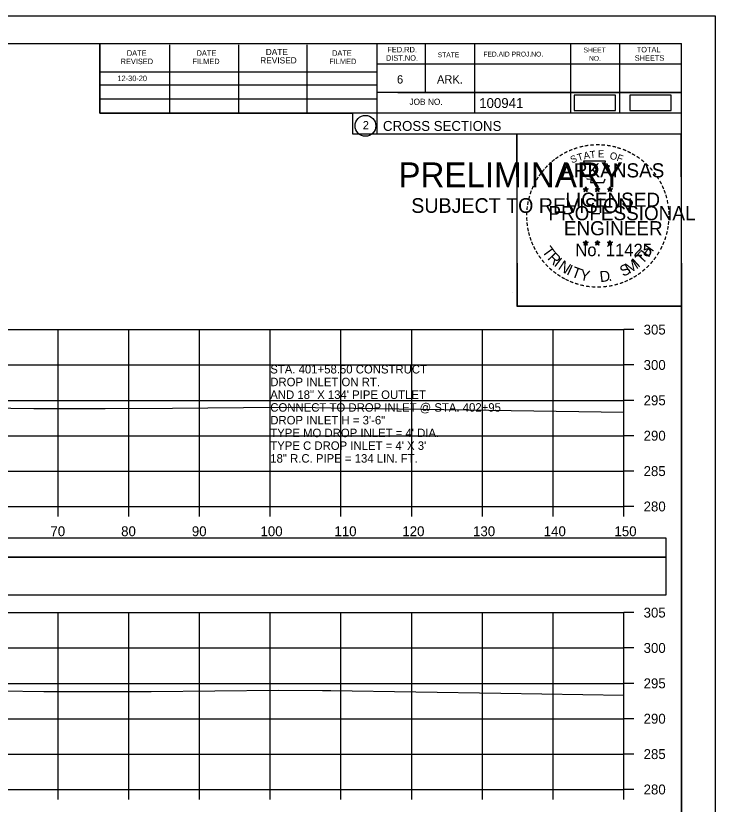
# Model space of a CAD drawing. Extents: x 1370538 to 1372872, y 376220 to 381127.
# Drawn here: x 1370772.6 to 1370871.5, y 376322.3 to 376433.8 of the extents above; entities that cross this region are included whole.
import ezdxf

# ---------------------------------------------------------------- set-up
doc = ezdxf.new("R2010")
doc.units = 0
for name, color, linetype in [('Default', 7, 'Continuous'), ('R_Border Notes', 7, 'Continuous'), ('R_Border PE', 7, 'Continuous'), ('R_Border Prem', 7, 'Continuous'), ('R_Dimension', 7, 'Continuous'), ('R_Grid', 7, 'Continuous'), ('R_No Plot', 7, 'Continuous'), ('R_Water Annot', 7, 'Continuous'), ('T_Detection Zones', 7, 'Continuous'), ('T_Indications', 7, 'Continuous'), ('T_Notes', 7, 'Continuous')]:
    doc.layers.add(name, color=color, linetype=linetype)

msp = doc.modelspace()

# ---------------------------------------------------------------- linework, layer by layer
at = {"layer": 'Default'}
for points in [[(1370851.6, 376420.37), (1370857.43, 376420.37), (1370857.43, 376422.56), (1370851.6, 376422.56)], [(1370859.47, 376420.37), (1370865.3, 376420.37), (1370865.3, 376422.56), (1370859.47, 376422.56)]]:
    msp.add_lwpolyline(points, close=True, dxfattribs=at)
at = {"layer": 'R_Border Notes'}
for p, q in [((1370550.61, 376429.87), (1370866.79, 376429.87)), ((1370784.53, 376419.99), (1370784.53, 376429.87)), ((1370794.39, 376419.99), (1370794.39, 376429.67)), ((1370804.15, 376419.99), (1370804.15, 376429.67)), ((1370813.83, 376419.99), (1370813.83, 376429.67)), ((1370823.69, 376429.87), (1370823.69, 376417.07)), ((1370830.53, 376429.87), (1370830.53, 376422.93)), ((1370837.47, 376429.87), (1370837.47, 376419.99)), ((1370851.05, 376429.87), (1370851.05, 376419.99)), ((1370857.99, 376429.87), (1370857.99, 376419.99)), ((1370866.79, 376224.41), (1370866.79, 376429.87)), ((1370866.79, 376426.93), (1370823.69, 376426.93)), ((1370866.79, 376426.95), (1370866.79, 376426.95)), ((1370784.53, 376425.85), (1370823.69, 376425.85)), ((1370784.53, 376423.99), (1370823.69, 376423.99)), ((1370866.79, 376422.93), (1370823.69, 376422.93)), ((1370826.65, 376422.93), (1370866.79, 376422.93)), ((1370784.53, 376419.99), (1370784.53, 376422.05)), ((1370784.53, 376422.05), (1370823.69, 376422.05)), ((1370866.79, 376419.99), (1370784.53, 376419.99)), ((1370823.69, 376417.07), (1370866.79, 376417.07))]:
    msp.add_line(p, q, dxfattribs=at)
msp.add_circle((1370822.07, 376418.21), 1.47, dxfattribs=at)
at = {"layer": 'R_Border Prem'}
for p, q in [((1370858.61, 376364.41), (1370858.61, 376389.41)), ((1370860.01, 376389.41), (1370858.61, 376389.41)), ((1370860.01, 376384.41), (1370858.61, 376384.41)), ((1370860.01, 376379.41), (1370858.61, 376379.41)), ((1370860.01, 376374.41), (1370858.61, 376374.41)), ((1370860.01, 376369.41), (1370858.61, 376369.41)), ((1370558.61, 376364.41), (1370858.61, 376364.41)), ((1370778.61, 376363.01), (1370778.61, 376364.41)), ((1370788.61, 376363.01), (1370788.61, 376364.41)), ((1370798.61, 376363.01), (1370798.61, 376364.41)), ((1370808.61, 376363.01), (1370808.61, 376364.41)), ((1370818.61, 376363.01), (1370818.61, 376364.41)), ((1370828.61, 376363.01), (1370828.61, 376364.41)), ((1370838.61, 376363.01), (1370838.61, 376364.41)), ((1370848.61, 376363.01), (1370848.61, 376364.41)), ((1370858.61, 376363.01), (1370858.61, 376364.41)), ((1370860.01, 376364.41), (1370858.61, 376364.41)), ((1370858.61, 376324.41), (1370858.61, 376349.41)), ((1370860.01, 376349.41), (1370858.61, 376349.41)), ((1370860.01, 376344.41), (1370858.61, 376344.41)), ((1370860.01, 376339.41), (1370858.61, 376339.41)), ((1370860.01, 376334.41), (1370858.61, 376334.41)), ((1370860.01, 376329.41), (1370858.61, 376329.41)), ((1370558.61, 376324.41), (1370858.61, 376324.41)), ((1370778.61, 376323.01), (1370778.61, 376324.41)), ((1370788.61, 376323.01), (1370788.61, 376324.41)), ((1370798.61, 376323.01), (1370798.61, 376324.41)), ((1370808.61, 376323.01), (1370808.61, 376324.41)), ((1370818.61, 376323.01), (1370818.61, 376324.41)), ((1370828.61, 376323.01), (1370828.61, 376324.41)), ((1370838.61, 376323.01), (1370838.61, 376324.41)), ((1370848.61, 376323.01), (1370848.61, 376324.41)), ((1370858.61, 376323.01), (1370858.61, 376324.41)), ((1370860.01, 376324.41), (1370858.61, 376324.41))]:
    msp.add_line(p, q, dxfattribs=at)
at = {"layer": 'R_Dimension'}
for points in [[(1370765.35, 376378.4), (1370775.16, 376378.26), (1370785.24, 376378.26), (1370794.79, 376378.29), (1370809.82, 376378.47), (1370814.99, 376378.41), (1370817.22, 376378.37), (1370858.61, 376377.74)], [(1370770.61, 376338.34), (1370776.58, 376338.25), (1370788.09, 376338.25), (1370791.77, 376338.26), (1370809.78, 376338.47), (1370815.98, 376338.41), (1370817.18, 376338.38), (1370841.24, 376338.02), (1370858.61, 376337.75)]]:
    msp.add_lwpolyline(points, dxfattribs=at)
at = {"layer": 'R_Grid'}
for p, q in [((1370558.61, 376389.41), (1370858.61, 376389.41)), ((1370778.61, 376364.41), (1370778.61, 376389.41)), ((1370788.61, 376364.41), (1370788.61, 376389.41)), ((1370798.61, 376364.41), (1370798.61, 376389.41)), ((1370808.61, 376364.41), (1370808.61, 376389.41)), ((1370818.61, 376364.41), (1370818.61, 376389.41)), ((1370828.61, 376364.41), (1370828.61, 376389.41)), ((1370838.61, 376364.41), (1370838.61, 376389.41)), ((1370848.61, 376364.41), (1370848.61, 376389.41)), ((1370858.61, 376364.41), (1370858.61, 376389.41)), ((1370558.61, 376384.41), (1370858.61, 376384.41)), ((1370558.61, 376379.41), (1370858.61, 376379.41)), ((1370558.61, 376374.41), (1370858.61, 376374.41)), ((1370558.61, 376369.41), (1370858.61, 376369.41)), ((1370558.61, 376364.41), (1370858.61, 376364.41)), ((1370558.61, 376349.41), (1370858.61, 376349.41)), ((1370778.61, 376324.41), (1370778.61, 376349.41)), ((1370788.61, 376324.41), (1370788.61, 376349.41)), ((1370798.61, 376324.41), (1370798.61, 376349.41)), ((1370808.61, 376324.41), (1370808.61, 376349.41)), ((1370818.61, 376324.41), (1370818.61, 376349.41)), ((1370828.61, 376324.41), (1370828.61, 376349.41)), ((1370838.61, 376324.41), (1370838.61, 376349.41)), ((1370848.61, 376324.41), (1370848.61, 376349.41)), ((1370858.61, 376324.41), (1370858.61, 376349.41)), ((1370558.61, 376344.41), (1370858.61, 376344.41)), ((1370558.61, 376339.41), (1370858.61, 376339.41)), ((1370558.61, 376334.41), (1370858.61, 376334.41)), ((1370558.61, 376329.41), (1370858.61, 376329.41)), ((1370558.61, 376324.41), (1370858.61, 376324.41))]:
    msp.add_line(p, q, dxfattribs=at)
at = {"layer": 'R_No Plot'}
for p, q in [((1370538.21, 376433.77), (1370871.54, 376433.77)), ((1370842.82, 376394.62), (1370842.82, 376394.62))]:
    msp.add_line(p, q, dxfattribs=at)
for points in [[(1370538.2, 376433.77), (1370871.54, 376433.77), (1370871.54, 376220.43), (1370538.2, 376220.43)], [(1370784.53, 376429.87), (1370784.53, 376419.99), (1370820.26, 376419.99), (1370820.26, 376417.07), (1370843.46, 376417.07), (1370843.46, 376392.74), (1370866.79, 376392.74), (1370866.79, 376224.41), (1370550.61, 376224.41), (1370550.61, 376429.87)], [(1370843.46, 376417.07), (1370866.67, 376417.07), (1370866.79, 376392.74), (1370843.58, 376392.74)]]:
    msp.add_lwpolyline(points, close=True, dxfattribs=at)
at = {"layer": 'T_Detection Zones'}
for points in [[(1370552.62, 376357.24), (1370864.59, 376357.24), (1370864.59, 376359.94), (1370552.62, 376359.94)], [(1370552.62, 376351.91), (1370864.59, 376351.91), (1370864.59, 376357.24), (1370552.62, 376357.24)]]:
    msp.add_lwpolyline(points, close=True, dxfattribs=at)
at = {"layer": 'T_Indications'}
for p, q in [((1370853.22, 376409.58), (1370853.18, 376409.33)), ((1370853.22, 376409.22), (1370853.22, 376409.58)), ((1370853.22, 376409.58), (1370853.27, 376409.33)), ((1370854.89, 376409.58), (1370854.85, 376409.33)), ((1370854.89, 376409.22), (1370854.89, 376409.58)), ((1370854.89, 376409.58), (1370854.94, 376409.33)), ((1370856.65, 376409.57), (1370856.61, 376409.32)), ((1370856.65, 376409.21), (1370856.65, 376409.57)), ((1370856.65, 376409.57), (1370856.7, 376409.32)), ((1370852.87, 376409.33), (1370853.22, 376409.22)), ((1370852.87, 376409.33), (1370853.12, 376409.28)), ((1370852.87, 376409.33), (1370853.11, 376409.21)), ((1370853, 376408.92), (1370853.22, 376409.22)), ((1370853, 376408.92), (1370853.13, 376409.17)), ((1370853, 376408.92), (1370853.22, 376409.14)), ((1370853.57, 376409.33), (1370853.22, 376409.22)), ((1370853.43, 376408.92), (1370853.22, 376409.22)), ((1370853.43, 376408.92), (1370853.22, 376409.14)), ((1370853.57, 376409.33), (1370853.28, 376409.28)), ((1370853.43, 376408.92), (1370853.3, 376409.21)), ((1370853.57, 376409.33), (1370853.36, 376409.23)), ((1370854.54, 376409.33), (1370854.89, 376409.22)), ((1370854.54, 376409.33), (1370854.79, 376409.28)), ((1370854.54, 376409.33), (1370854.78, 376409.21)), ((1370854.67, 376408.92), (1370854.89, 376409.22)), ((1370854.67, 376408.92), (1370854.8, 376409.17)), ((1370854.67, 376408.92), (1370854.89, 376409.14)), ((1370855.24, 376409.33), (1370854.89, 376409.22)), ((1370855.1, 376408.92), (1370854.89, 376409.22)), ((1370855.1, 376408.92), (1370854.89, 376409.14)), ((1370855.24, 376409.33), (1370854.95, 376409.28)), ((1370855.1, 376408.92), (1370854.97, 376409.21)), ((1370855.24, 376409.33), (1370855.03, 376409.23)), ((1370856.31, 376409.32), (1370856.65, 376409.21)), ((1370856.31, 376409.32), (1370856.56, 376409.27)), ((1370856.31, 376409.32), (1370856.54, 376409.2)), ((1370856.44, 376408.91), (1370856.65, 376409.21)), ((1370856.44, 376408.91), (1370856.56, 376409.15)), ((1370856.44, 376408.91), (1370856.65, 376409.13)), ((1370857, 376409.32), (1370856.65, 376409.21)), ((1370856.87, 376408.91), (1370856.65, 376409.21)), ((1370856.87, 376408.91), (1370856.65, 376409.12)), ((1370857, 376409.32), (1370856.72, 376409.27)), ((1370856.87, 376408.91), (1370856.73, 376409.2)), ((1370857, 376409.32), (1370856.8, 376409.22)), ((1370853.22, 376402.01), (1370853.18, 376401.76)), ((1370853.22, 376401.65), (1370853.22, 376402.01)), ((1370853.22, 376402.01), (1370853.27, 376401.76)), ((1370854.89, 376402.01), (1370854.84, 376401.76)), ((1370854.89, 376401.65), (1370854.89, 376402.01)), ((1370854.89, 376402.01), (1370854.93, 376401.76)), ((1370856.65, 376402), (1370856.61, 376401.75)), ((1370856.65, 376401.64), (1370856.65, 376402)), ((1370856.65, 376402), (1370856.7, 376401.75)), ((1370852.87, 376401.76), (1370853.22, 376401.65)), ((1370852.87, 376401.76), (1370853.12, 376401.71)), ((1370852.87, 376401.76), (1370853.1, 376401.63)), ((1370853, 376401.35), (1370853.22, 376401.65)), ((1370853, 376401.35), (1370853.13, 376401.59)), ((1370853, 376401.35), (1370853.21, 376401.57)), ((1370853.43, 376401.35), (1370853.21, 376401.56)), ((1370853.56, 376401.76), (1370853.22, 376401.65)), ((1370853.43, 376401.35), (1370853.22, 376401.65)), ((1370853.56, 376401.76), (1370853.28, 376401.71)), ((1370853.43, 376401.35), (1370853.29, 376401.64)), ((1370853.56, 376401.76), (1370853.36, 376401.65)), ((1370854.54, 376401.76), (1370854.89, 376401.65)), ((1370854.54, 376401.76), (1370854.79, 376401.71)), ((1370854.54, 376401.76), (1370854.77, 376401.63)), ((1370854.67, 376401.35), (1370854.89, 376401.65)), ((1370854.67, 376401.35), (1370854.8, 376401.59)), ((1370854.67, 376401.35), (1370854.88, 376401.57)), ((1370855.1, 376401.35), (1370854.88, 376401.56)), ((1370855.23, 376401.76), (1370854.89, 376401.65)), ((1370855.1, 376401.35), (1370854.89, 376401.65)), ((1370855.23, 376401.76), (1370854.95, 376401.71)), ((1370855.1, 376401.35), (1370854.96, 376401.64)), ((1370855.23, 376401.76), (1370855.03, 376401.65)), ((1370856.3, 376401.75), (1370856.65, 376401.64)), ((1370856.3, 376401.75), (1370856.56, 376401.7)), ((1370856.3, 376401.75), (1370856.54, 376401.62)), ((1370856.44, 376401.34), (1370856.65, 376401.64)), ((1370856.44, 376401.34), (1370856.56, 376401.58)), ((1370856.44, 376401.34), (1370856.65, 376401.56)), ((1370857, 376401.75), (1370856.65, 376401.64)), ((1370856.87, 376401.34), (1370856.65, 376401.64)), ((1370856.87, 376401.34), (1370856.65, 376401.55)), ((1370857, 376401.75), (1370856.71, 376401.7)), ((1370856.87, 376401.34), (1370856.73, 376401.63)), ((1370857, 376401.75), (1370856.8, 376401.64))]:
    msp.add_line(p, q, dxfattribs=at)
for points in [[(1370852.91, 376413.21), (1370853.18, 376412.38)], [(1370856.42, 376412.29), (1370856.57, 376412.57), (1370855.88, 376412.55), (1370856.03, 376413.21), (1370852.91, 376413.21)], [(1370853.4, 376410.78), (1370853.4, 376410.7), (1370853.97, 376410.68), (1370853.91, 376410.21), (1370855.78, 376410.21), (1370855.98, 376410.74)], [(1370853.22, 376409.58), (1370853.43, 376408.92), (1370852.87, 376409.33), (1370853.57, 376409.33), (1370853, 376408.92), (1370853.22, 376409.58)], [(1370854.89, 376409.58), (1370855.1, 376408.92), (1370854.54, 376409.33), (1370855.24, 376409.33), (1370854.67, 376408.92), (1370854.89, 376409.58)], [(1370856.65, 376409.57), (1370856.87, 376408.91), (1370856.31, 376409.32), (1370857, 376409.32), (1370856.44, 376408.91), (1370856.65, 376409.57)], [(1370853.22, 376402.01), (1370853.43, 376401.35), (1370852.87, 376401.76), (1370853.56, 376401.76), (1370853, 376401.35), (1370853.22, 376402.01)], [(1370854.89, 376402.01), (1370855.1, 376401.35), (1370854.54, 376401.76), (1370855.23, 376401.76), (1370854.67, 376401.35), (1370854.89, 376402.01)], [(1370856.65, 376402), (1370856.87, 376401.34), (1370856.3, 376401.75), (1370857, 376401.75), (1370856.44, 376401.34), (1370856.65, 376402)]]:
    msp.add_lwpolyline(points, dxfattribs=at)
for centre, radius in [((1370853.22, 376409.22), 0.172), ((1370853.22, 376409.22), 0.145), ((1370853.22, 376409.22), 0.116), ((1370853.22, 376409.22), 0.0991), ((1370853.22, 376409.22), 0.0747), ((1370853.22, 376409.22), 0.0495), ((1370853.22, 376409.22), 0.0296), ((1370854.89, 376409.22), 0.172), ((1370854.89, 376409.22), 0.145), ((1370854.89, 376409.22), 0.116), ((1370854.89, 376409.22), 0.0991), ((1370854.89, 376409.22), 0.0747), ((1370854.89, 376409.22), 0.0495), ((1370854.89, 376409.22), 0.0296), ((1370856.65, 376409.21), 0.172), ((1370856.65, 376409.21), 0.145), ((1370856.65, 376409.21), 0.116), ((1370856.65, 376409.21), 0.0991), ((1370856.65, 376409.21), 0.0747), ((1370856.65, 376409.21), 0.0495), ((1370856.65, 376409.21), 0.0296), ((1370853.22, 376401.64), 0.172), ((1370853.22, 376401.64), 0.145), ((1370853.22, 376401.64), 0.116), ((1370854.88, 376401.64), 0.172), ((1370854.88, 376401.64), 0.145), ((1370854.88, 376401.64), 0.116), ((1370856.65, 376401.63), 0.172), ((1370856.65, 376401.63), 0.145), ((1370853.22, 376401.64), 0.0991), ((1370853.22, 376401.64), 0.0747), ((1370853.22, 376401.64), 0.0495), ((1370853.22, 376401.64), 0.0296), ((1370854.88, 376401.64), 0.0991), ((1370854.88, 376401.64), 0.0747), ((1370854.88, 376401.64), 0.0495), ((1370854.88, 376401.64), 0.0296), ((1370856.65, 376401.63), 0.116), ((1370856.65, 376401.63), 0.0991), ((1370856.65, 376401.63), 0.0747), ((1370856.65, 376401.63), 0.0495), ((1370856.65, 376401.63), 0.0296)]:
    msp.add_circle(centre, radius, dxfattribs=at)

# ---------------------------------------------------------------- texts
at = {"layer": 'R_Border Notes'}
for s, height, p in [('DATE', 0.782, (1370788.33, 376428.11)), ('DATE', 0.782, (1370798.19, 376428.11)), ('DATE', 0.879, (1370807.97, 376428.21)), ('DATE', 0.782, (1370817.35, 376428.11)), ('FED.RD.', 0.782, (1370825.17, 376428.59)), ('STATE', 0.684, (1370832.29, 376427.91)), ('FED.AID PROJ.NO.', 0.684, (1370838.75, 376428.01)), ('SHEET', 0.684, (1370852.91, 376428.59)), ('TOTAL', 0.782, (1370860.43, 376428.59)), ('REVISED', 0.782, (1370787.45, 376426.93)), ('FILMED', 0.782, (1370797.61, 376426.93)), ('REVISED', 0.879, (1370807.19, 376427.03)), ('FILMED', 0.782, (1370816.95, 376426.93)), ('DIST.NO.', 0.782, (1370824.97, 376427.41)), ('NO.', 0.684, (1370853.69, 376427.41)), ('SHEETS', 0.782, (1370860.15, 376427.41)), ('6', 1.17, (1370826.53, 376424.19)), ('ARK.', 1.172, (1370832.19, 376424.19)), ('JOB NO.', 0.879, (1370828.29, 376421.17)), ('100941', 1.4, (1370838.16, 376420.73)), ('2', 1.17, (1370821.69, 376417.72)), ('CROSS SECTIONS', 1.4, (1370824.55, 376417.5))]:
    msp.add_text(s, height=height, rotation=360, dxfattribs=at).set_placement(p)
msp.add_text('12-30-20', height=0.78, dxfattribs=at).set_placement((1370787, 376424.53))
at = {"layer": 'R_Border PE'}
for s, p in [('305', (1370861.41, 376388.71)), ('300', (1370861.41, 376383.71)), ('295', (1370861.41, 376378.71)), ('290', (1370861.41, 376373.71)), ('285', (1370861.41, 376368.71)), ('280', (1370861.41, 376363.71)), ('70', (1370777.52, 376360.21)), ('80', (1370787.52, 376360.21)), ('90', (1370797.52, 376360.21)), ('100', (1370807.23, 376360.21)), ('110', (1370817.69, 376360.21)), ('120', (1370827.29, 376360.21)), ('130', (1370837.29, 376360.21)), ('140', (1370847.29, 376360.21)), ('150', (1370857.29, 376360.21)), ('305', (1370861.41, 376348.71)), ('300', (1370861.41, 376343.71)), ('295', (1370861.41, 376338.71)), ('290', (1370861.41, 376333.71)), ('285', (1370861.41, 376328.71)), ('280', (1370861.41, 376323.71))]:
    msp.add_text(s, height=1.4, dxfattribs=at).set_placement(p)
at = {"layer": 'R_Water Annot'}
for s, p in [('STA. 401+58.50 CONSTRUCT', (1370808.61, 376383.21)), ('DROP INLET ON RT.', (1370808.61, 376381.41)), ('AND 18" X 134\' PIPE OUTLET', (1370808.61, 376379.61)), ('CONNECT TO DROP INLET @ STA. 402+95', (1370808.61, 376377.81)), ('DROP INLET H = 3\'-6"', (1370808.61, 376376.01)), ("TYPE MO DROP INLET = 4' DIA.", (1370808.61, 376374.21)), ("TYPE C DROP INLET = 4' X 3'", (1370808.61, 376372.41)), ('18" R.C. PIPE = 134 LIN. FT.', (1370808.61, 376370.61))]:
    msp.add_text(s, height=1.2, dxfattribs=at).set_placement(p)
at = {"layer": 'T_Indications'}
for s, height, rotation, p in [('-', 1.6, 19.1761, (1370851.66, 376414.33)), ('-', 1.6, 13.6301, (1370852.41, 376414.58)), ('-', 1.6, 10.2193, (1370853.09, 376414.74)), ('-', 1.6, 5.8968, (1370853.82, 376414.85)), ('-', 1.6, 0.1862, (1370854.59, 376414.92)), ('-', 1.6, 357.743, (1370855.31, 376414.91)), ('-', 1.6, 352.1617, (1370856.06, 376414.85)), ('-', 1.6, 347.2049, (1370856.78, 376414.74)), ('-', 1.6, 342.3362, (1370857.41, 376414.58)), ('-', 1.6, 34.0636, (1370849.8, 376413.38)), ('-', 1.6, 28.7918, (1370850.39, 376413.75)), ('-', 1.6, 24.3072, (1370851.03, 376414.07)), ('S', 1, 21.594, (1370851.27, 376412.89)), ('T', 1, 16.4036, (1370852.18, 376413.22)), ('A', 1, 11.2132, (1370853.01, 376413.47)), ('T', 1, 6.0228, (1370853.86, 376413.63)), ('E', 1, 0.8323, (1370854.96, 376413.74)), ('O', 1, 350.4515, (1370856.57, 376413.53)), ('F', 1, 340.0707, (1370857.52, 376413.31)), ('-', 1.6, 337.8551, (1370858.15, 376414.36)), ('-', 1.6, 334.1211, (1370858.78, 376414.09)), ('-', 1.6, 329.6409, (1370859.36, 376413.8)), ('-', 1.6, 42.9622, (1370848.31, 376412.19)), ('-', 1.6, 38.9507, (1370848.74, 376412.61)), ('-', 1.6, 36.2317, (1370849.22, 376412.98)), ('ARKANSAS', 2, 360, (1370849.77, 376410.92)), ('-', 1.6, 325.8627, (1370860, 376413.44)), ('-', 1.6, 320.5297, (1370860.61, 376413.02)), ('-', 1.6, 315.5786, (1370861.21, 376412.53)), ('-', 1.6, 50.6142, (1370847.46, 376411.22)), ('-', 1.6, 48.423, (1370847.86, 376411.71)), ('-', 1.6, 309.8797, (1370861.78, 376411.98)), ('-', 1.6, 58.0706, (1370846.72, 376410.13)), ('-', 1.6, 54.2325, (1370847.05, 376410.66)), ('-', 1.6, 306.6522, (1370862.3, 376411.38)), ('-', 1.4, 303.6753, (1370862.79, 376410.81)), ('-', 1.6, 67.7743, (1370846.15, 376408.91)), ('-', 1.6, 62.8713, (1370846.41, 376409.52)), ('-', 1.6, 299.6684, (1370863.11, 376410.2)), ('-', 1.6, 294.6628, (1370863.43, 376409.59)), ('-', 1.6, 72.3945, (1370845.93, 376408.28)), ('LICENSED', 2, 360, (1370850.36, 376406.77)), ('DWB', 0.01, 360, (1370853.21, 376409.21)), ('DWB', 0.01, 360, (1370854.88, 376409.21)), ('DWB', 0.01, 360, (1370856.64, 376409.2)), ('-', 1.6, 290.5728, (1370863.69, 376409.01)), ('-', 1.6, 285.1233, (1370863.92, 376408.43)), ('-', 1.6, 81.2013, (1370845.6, 376406.85)), ('-', 1.6, 75.461, (1370845.73, 376407.56)), ('-', 1.6, 280.5493, (1370864.12, 376407.69)), ('-', 1.6, 85.1863, (1370845.52, 376406.16)), ('PROFESSIONAL', 2, 360, (1370847.94, 376404.87)), ('-', 1.6, 276.5962, (1370864.28, 376406.92)), ('-', 1.6, 94.1959, (1370845.53, 376404.73)), ('-', 1.6, 89.0622, (1370845.5, 376405.46)), ('-', 1.6, 274.3301, (1370864.34, 376406.2)), ('-', 1.6, 269.9407, (1370864.38, 376405.57)), ('-', 1.6, 98.9479, (1370845.61, 376404.06)), ('ENGINEER', 2, 360, (1370850.13, 376402.74)), ('-', 1.6, 260.9953, (1370864.29, 376404.25)), ('-', 1.6, 263.5172, (1370864.36, 376404.9)), ('-', 1.6, 101.7149, (1370845.74, 376403.33)), ('-', 1.6, 105.4578, (1370845.9, 376402.74)), ('-', 1.6, 255.7626, (1370864.18, 376403.57)), ('-', 1.6, 109.0874, (1370846.12, 376402.11)), ('-', 1.6, 114.0643, (1370846.37, 376401.51)), ('-', 1.6, 247.8887, (1370863.77, 376402.18)), ('-', 1.6, 252.8681, (1370864, 376402.85)), ('-', 1.6, 115.7289, (1370846.68, 376400.89)), ('T', 1.54, 306.0406, (1370846.98, 376400.48)), ('No. 11425', 1.757, 360, (1370851.75, 376399.79)), ('DWB', 0.01, 360, (1370853.2, 376401.64)), ('DWB', 0.01, 360, (1370854.87, 376401.64)), ('DWB', 0.01, 360, (1370856.64, 376401.63)), ('H', 1.54, 54.6088, (1370862.1, 376399.52)), ('-', 1.6, 244.6197, (1370863.51, 376401.55)), ('-', 1.6, 120.4471, (1370847.03, 376400.31)), ('-', 1.6, 125.8934, (1370847.44, 376399.74)), ('R', 1.54, 314.005, (1370847.74, 376399.44)), ('I', 1.54, 321.9694, (1370848.64, 376398.5)), ('T', 1.54, 46.6444, (1370861.21, 376398.58)), ('-', 1.6, 233.8452, (1370862.72, 376400.14)), ('-', 1.6, 239.0712, (1370863.12, 376400.8)), ('-', 1.6, 130.7181, (1370847.9, 376399.19)), ('-', 1.6, 134.2238, (1370848.42, 376398.65)), ('N', 1.54, 326.5002, (1370849.21, 376398.03)), ('I', 1.54, 335.3603, (1370850.41, 376397.25)), ('S', 1.54, 26.9312, (1370858.52, 376396.85)), ('M', 1.54, 32.6563, (1370859.36, 376397.25)), ('I', 1.54, 42.1136, (1370860.64, 376398.1)), ('-', 1.6, 225.7653, (1370861.81, 376399.01)), ('-', 1.6, 231.2538, (1370862.29, 376399.58)), ('-', 1.6, 138.9338, (1370848.94, 376398.18)), ('-', 1.6, 144.6463, (1370849.5, 376397.78)), ('T', 1.54, 339.8912, (1370851.08, 376396.92)), ('Y', 1.54, 347.8556, (1370852.29, 376396.47)), ('D', 1.54, 6.3969, (1370855.28, 376396.11)), ('-', 1.6, 215.7363, (1370860.74, 376398.03)), ('-', 1.6, 221.0851, (1370861.28, 376398.51)), ('-', 1.6, 148.0898, (1370850.06, 376397.41)), ('-', 1.6, 151.5704, (1370850.64, 376397.08)), ('-', 1.6, 154.6002, (1370851.16, 376396.83)), ('-', 1.6, 158.5612, (1370851.78, 376396.58)), ('.', 1.54, 13.7642, (1370856.47, 376396.24)), ('-', 1.6, 204.2516, (1370859.02, 376396.98)), ('-', 1.6, 207.3568, (1370859.64, 376397.3)), ('-', 1.6, 212.2491, (1370860.2, 376397.65)), ('-', 1.6, 162.7983, (1370852.47, 376396.37)), ('-', 1.6, 167.5555, (1370853.19, 376396.2)), ('-', 1.6, 173.1155, (1370853.96, 376396.09)), ('-', 1.6, 176.5183, (1370854.71, 376396.04)), ('-', 1.6, 181.5918, (1370855.45, 376396.06)), ('-', 1.6, 185.8167, (1370856.26, 376396.14)), ('-', 1.6, 191.2858, (1370856.99, 376396.27)), ('-', 1.6, 195.4743, (1370857.72, 376396.47)), ('-', 1.6, 200.7184, (1370858.4, 376396.71))]:
    msp.add_text(s, height=height, rotation=rotation, dxfattribs=at).set_placement(p)
at = {"layer": 'T_Notes'}
for s, height, p in [('PRELIMINARY', 3.5, (1370826.74, 376409.54)), ('DWB', 0.01, (1370827.48, 376411.39)), ('SUBJECT TO REVISION', 2.0751, (1370828.55, 376405.91))]:
    msp.add_text(s, height=height, rotation=360, dxfattribs=at).set_placement(p)

doc.saveas('drawing.dxf')
